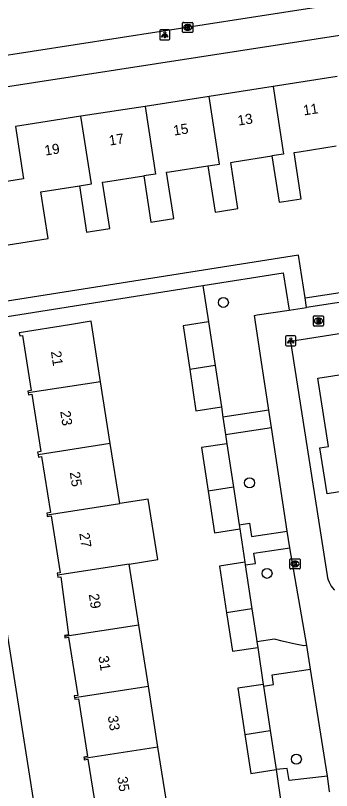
# Model space of a CAD drawing. Extents: x 160077 to 160945, y 386481 to 387498.
# Drawn here: x 160283.4 to 160314.4, y 387277.3 to 387353.4 of the extents above; entities that cross this region are included whole.
import ezdxf

# ---------------------------------------------------------------- set-up
doc = ezdxf.new("R2010")
doc.units = 0
for name, color, linetype in [('IMGEO_Boom', 7, 'Continuous'), ('IMGEO_Brandkraan', 7, 'Continuous'), ('IMGEO_Groenvoorziening', 7, 'Continuous'), ('IMGEO_Haag', 7, 'Continuous'), ('IMGEO_Hek', 7, 'Continuous'), ('IMGEO_Kolk', 7, 'Continuous'), ('IMGEO_Lichtpunt', 7, 'Continuous'), ('IMGEO_Pand', 7, 'Continuous'), ('IMGEO_Pand_nummerreeks', 7, 'Continuous'), ('IMGEO_Rijbaan_lokaal_open', 7, 'Continuous'), ('IMGEO_Voetpad_open', 7, 'Continuous')]:
    doc.layers.add(name, color=color, linetype=linetype)

msp = doc.modelspace()

# ---------------------------------------------------------------- linework, layer by layer
at = {"layer": 'IMGEO_Boom'}
for centre in [(160303.826, 387325.258), (160306.399, 387307.549), (160308.114, 387298.661), (160310.999, 387280.425)]:
    msp.add_circle(centre, 0.489, dxfattribs=at)
at = {"layer": 'IMGEO_Brandkraan'}
for p, q in [((160312.664, 387323.017), (160312.664, 387323.869)), ((160312.739, 387323.943), (160313.591, 387323.943)), ((160313.152, 387323.723), (160313.177, 387323.723)), ((160313.665, 387323.869), (160313.665, 387323.017)), ((160313.591, 387322.943), (160312.739, 387322.943)), ((160313.175, 387323.163), (160313.15, 387323.163))]:
    msp.add_line(p, q, dxfattribs=at)
for points in [[(160312.664, 387323.017), (160312.664, 387323.869)], [(160312.739, 387323.943), (160313.591, 387323.943)], [(160313.012, 387323.643), (160313.012, 387323.243), (160313.225, 387323.243)], [(160313.243, 387323.643), (160313.012, 387323.643)], [(160313.191, 387323.562), (160313.137, 387323.562), (160313.137, 387323.486)], [(160313.137, 387323.486), (160313.19, 387323.486)], [(160313.665, 387323.869), (160313.665, 387323.017)], [(160313.591, 387322.943), (160312.739, 387322.943)], [(160313.199, 387323.41), (160313.137, 387323.41), (160313.137, 387323.329)], [(160313.137, 387323.329), (160313.199, 387323.329)]]:
    msp.add_lwpolyline(points, dxfattribs=at)
for centre, radius, start, end in [((160312.741, 387323.867), 0.0765, 91.55205, 178.44795), ((160312.741, 387323.867), 0.0765, 91.55205, 178.44795), ((160313.192, 387323.524), 0.0379, 267.82845, 90.93552), ((160313.247, 387323.498), 0.145, 59.4692, 91.53667), ((160313.272, 387323.545), 0.0922, 285.51372, 58.15012), ((160313.589, 387323.867), 0.0765, 1.55205, 88.44795), ((160313.589, 387323.867), 0.0765, 1.55205, 88.44795), ((160312.741, 387323.019), 0.0765, 181.55205, 268.44795), ((160312.741, 387323.019), 0.0765, 181.55205, 268.44795), ((160313.2, 387323.369), 0.0404, 269.87594, 90.50774), ((160313.231, 387323.494), 0.251, 268.66757, 293.53466), ((160313.277, 387323.353), 0.105, 301.31148, 78.98903), ((160313.589, 387323.019), 0.0765, 271.55205, 358.44795), ((160313.589, 387323.019), 0.0765, 271.55205, 358.44795)]:
    msp.add_arc(centre, radius, start, end, dxfattribs=at)
for centre, major_axis, ratio, start_param, end_param in [((160313.151, 387323.443), (-0.387, 0.002), 0.722429, 4.712389, 7.853982), ((160313.176, 387323.443), (-0.39, 0.002), 0.717154, 1.570796, 4.712389)]:
    msp.add_ellipse(centre, major_axis=major_axis, ratio=ratio, start_param=start_param, end_param=end_param, dxfattribs=at)
at = {"layer": 'IMGEO_Groenvoorziening'}
for points in [[(160301.814, 387326.925), (160302.357, 387323.353)], [(160303.628, 387314.996), (160303.781, 387313.992)], [(160304.04, 387312.282), (160304.176, 387311.391)]]:
    msp.add_lwpolyline(points, dxfattribs=at)
at = {"layer": 'IMGEO_Haag'}
msp.add_lwpolyline([(160311.864, 387325.704), (160323.038, 387327.4), (160323.143, 387326.454)], dxfattribs=at)
at = {"layer": 'IMGEO_Hek'}
msp.add_lwpolyline([(160311.864, 387325.704), (160323.038, 387327.4)], dxfattribs=at)
at = {"layer": 'IMGEO_Kolk'}
for p, q in [((160299.825, 387351.831), (160299.825, 387352.683)), ((160299.9, 387352.757), (160300.752, 387352.757)), ((160300.313, 387352.537), (160300.338, 387352.537)), ((160300.826, 387352.683), (160300.826, 387351.831)), ((160300.752, 387351.757), (160299.9, 387351.757)), ((160300.336, 387351.977), (160300.311, 387351.977)), ((160310.365, 387299.169), (160310.365, 387300.021)), ((160310.44, 387300.095), (160311.292, 387300.095)), ((160311.366, 387300.021), (160311.366, 387299.169)), ((160310.876, 387299.315), (160310.851, 387299.315)), ((160310.853, 387299.875), (160310.878, 387299.875)), ((160311.292, 387299.095), (160310.44, 387299.095))]:
    msp.add_line(p, q, dxfattribs=at)
for points in [[(160299.825, 387351.831), (160299.825, 387352.683)], [(160299.9, 387352.757), (160300.752, 387352.757)], [(160300.146, 387352.457), (160300.269, 387352.457), (160300.269, 387352.306), (160300.399, 387352.457), (160300.563, 387352.457), (160300.417, 387352.306), (160300.57, 387352.057), (160300.418, 387352.057), (160300.333, 387352.221), (160300.269, 387352.154), (160300.269, 387352.057), (160300.146, 387352.057), (160300.146, 387352.457)], [(160300.826, 387352.683), (160300.826, 387351.831)], [(160300.752, 387351.757), (160299.9, 387351.757)], [(160310.365, 387299.169), (160310.365, 387300.021)], [(160310.44, 387300.095), (160311.292, 387300.095)], [(160311.366, 387300.021), (160311.366, 387299.169)], [(160310.686, 387299.795), (160310.809, 387299.795), (160310.809, 387299.644), (160310.939, 387299.795), (160311.103, 387299.795), (160310.957, 387299.644), (160311.11, 387299.395), (160310.958, 387299.395), (160310.873, 387299.559), (160310.809, 387299.492), (160310.809, 387299.395), (160310.686, 387299.395), (160310.686, 387299.795)], [(160311.292, 387299.095), (160310.44, 387299.095)]]:
    msp.add_lwpolyline(points, dxfattribs=at)
for centre, start, end in [((160299.902, 387352.681), 91.55205, 178.44795), ((160299.902, 387352.681), 91.55205, 178.44795), ((160300.75, 387352.681), 1.55205, 88.44795), ((160300.75, 387352.681), 1.55205, 88.44795), ((160299.902, 387351.833), 181.55205, 268.44795), ((160299.902, 387351.833), 181.55205, 268.44795), ((160300.75, 387351.833), 271.55205, 358.44795), ((160300.75, 387351.833), 271.55205, 358.44795), ((160310.442, 387300.019), 91.55205, 178.44795), ((160310.442, 387300.019), 91.55205, 178.44795), ((160311.29, 387300.019), 1.55205, 88.44795), ((160311.29, 387300.019), 1.55205, 88.44795), ((160310.442, 387299.171), 181.55205, 268.44795), ((160310.442, 387299.171), 181.55205, 268.44795), ((160311.29, 387299.171), 271.55205, 358.44795), ((160311.29, 387299.171), 271.55205, 358.44795)]:
    msp.add_arc(centre, 0.0765, start, end, dxfattribs=at)
for centre, major_axis, ratio, start_param, end_param in [((160300.312, 387352.257), (-0.387, 0.002), 0.722429, 4.712389, 7.853982), ((160300.337, 387352.257), (-0.39, 0.002), 0.717154, 1.570796, 4.712389), ((160310.852, 387299.595), (-0.387, 0.002), 0.722429, 4.712389, 7.853982), ((160310.877, 387299.595), (-0.39, 0.002), 0.717154, 1.570796, 4.712389)]:
    msp.add_ellipse(centre, major_axis=major_axis, ratio=ratio, start_param=start_param, end_param=end_param, dxfattribs=at)
at = {"layer": 'IMGEO_Lichtpunt'}
for p, q in [((160297.57, 387351.936), (160297.57, 387351.129)), ((160297.57, 387351.936), (160297.57, 387351.129)), ((160298.472, 387352.031), (160297.664, 387352.031)), ((160298.472, 387352.031), (160297.664, 387352.031)), ((160298.566, 387351.129), (160298.566, 387351.936)), ((160298.566, 387351.129), (160298.566, 387351.936)), ((160297.664, 387351.035), (160298.472, 387351.035)), ((160297.664, 387351.035), (160298.472, 387351.035)), ((160310.846, 387321.987), (160310.038, 387321.987)), ((160310.846, 387321.987), (160310.038, 387321.987)), ((160309.944, 387321.892), (160309.944, 387321.085)), ((160309.944, 387321.892), (160309.944, 387321.085)), ((160310.94, 387321.085), (160310.94, 387321.892)), ((160310.94, 387321.085), (160310.94, 387321.892)), ((160310.038, 387320.991), (160310.846, 387320.991)), ((160310.038, 387320.991), (160310.846, 387320.991))]:
    msp.add_line(p, q, dxfattribs=at)
for points in [[(160297.944, 387351.6), (160297.983, 387351.572), (160297.795, 387351.31), (160297.757, 387351.337), (160297.944, 387351.6)], [(160298.046, 387351.552), (160298.093, 387351.552), (160298.093, 387351.23), (160298.046, 387351.23), (160298.046, 387351.552)], [(160298.156, 387351.572), (160298.194, 387351.599), (160298.381, 387351.337), (160298.342, 387351.309), (160298.156, 387351.572)], [(160310.318, 387321.556), (160310.357, 387321.528), (160310.169, 387321.266), (160310.131, 387321.293), (160310.318, 387321.556)], [(160310.42, 387321.508), (160310.467, 387321.508), (160310.467, 387321.186), (160310.42, 387321.186), (160310.42, 387321.508)], [(160310.53, 387321.528), (160310.568, 387321.555), (160310.755, 387321.293), (160310.716, 387321.265), (160310.53, 387321.528)]]:
    msp.add_lwpolyline(points, dxfattribs=at)
for centre in [(160298.069, 387351.734), (160310.443, 387321.69)]:
    msp.add_circle(centre, 0.0994, dxfattribs=at)
for centre, start, end in [((160297.664, 387351.936), 90, 180), ((160297.664, 387351.936), 90, 180), ((160298.472, 387351.936), 0, 90), ((160298.472, 387351.936), 0, 90), ((160297.664, 387351.129), 180, 270), ((160297.664, 387351.129), 180, 270), ((160298.472, 387351.129), 270, 0), ((160298.472, 387351.129), 270, 360), ((160310.038, 387321.892), 90, 180), ((160310.038, 387321.892), 90, 180), ((160310.846, 387321.892), 0, 90), ((160310.846, 387321.892), 0, 90), ((160310.038, 387321.085), 180, 270), ((160310.038, 387321.085), 180, 270), ((160310.846, 387321.085), 270, 0), ((160310.846, 387321.085), 270, 360)]:
    msp.add_arc(centre, 0.0946, start, end, dxfattribs=at)
at = {"layer": 'IMGEO_Pand'}
for points in [[(160315.01, 387347.441), (160308.715, 387346.464)], [(160308.715, 387346.464), (160302.42, 387345.486)], [(160308.715, 387346.464), (160309.747, 387339.817), (160308.596, 387339.638)], [(160302.42, 387345.486), (160296.126, 387344.509)], [(160302.299, 387338.662), (160303.452, 387338.839), (160302.42, 387345.486)], [(160296.126, 387344.509), (160289.831, 387343.531)], [(160296.126, 387344.509), (160297.158, 387337.865), (160295.999, 387337.684)], [(160289.831, 387343.531), (160283.396, 387342.532), (160284.197, 387337.379), (160280.249, 387336.766), (160281.193, 387330.687), (160286.6, 387331.526), (160285.887, 387336.114), (160289.677, 387336.703)], [(160289.677, 387336.703), (160290.862, 387336.887), (160289.831, 387343.531)], [(160308.596, 387339.638), (160309.301, 387335.096), (160309.752, 387335.166), (160311.477, 387335.434), (160310.771, 387339.978), (160311.274, 387340.056), (160314.892, 387340.618)], [(160302.299, 387338.662), (160303.004, 387334.119), (160303.459, 387334.19), (160305.249, 387334.468), (160304.543, 387339.011), (160304.902, 387339.067), (160308.596, 387339.638)], [(160295.999, 387337.684), (160296.705, 387333.141), (160297.097, 387333.202), (160298.955, 387333.49), (160298.249, 387338.034), (160298.519, 387338.076), (160302.299, 387338.662)], [(160289.677, 387336.703), (160290.383, 387332.159), (160290.783, 387332.221), (160292.661, 387332.513), (160291.955, 387337.056), (160292.25, 387337.102), (160295.999, 387337.684)], [(160291.759, 387317.481), (160290.828, 387323.406), (160288.707, 387323.071), (160283.768, 387322.29), (160283.818, 387321.973), (160284.079, 387322.015), (160284.935, 387316.602), (160284.617, 387316.552), (160284.644, 387316.378)], [(160302.357, 387323.353), (160299.861, 387322.974), (160300.516, 387318.668)], [(160302.357, 387323.353), (160303.011, 387319.054)], [(160303.011, 387319.054), (160300.516, 387318.668)], [(160303.011, 387319.054), (160303.628, 387314.996)], [(160300.516, 387318.668), (160301.133, 387314.617), (160303.628, 387314.996)], [(160319.696, 387311.979), (160315.535, 387311.328), (160316.239, 387306.829), (160314.021, 387306.482), (160313.317, 387310.981), (160314.16, 387311.113), (160313.112, 387317.809), (160319.627, 387318.828)], [(160291.759, 387317.481), (160284.644, 387316.378)], [(160292.712, 387311.415), (160291.759, 387317.481)], [(160284.644, 387316.378), (160284.672, 387316.203), (160284.998, 387316.255), (160285.89, 387310.612), (160285.576, 387310.562), (160285.615, 387310.315)], [(160292.712, 387311.415), (160285.615, 387310.315)], [(160293.639, 387305.518), (160292.712, 387311.415)], [(160304.176, 387311.391), (160301.682, 387311.012), (160302.335, 387306.725)], [(160304.176, 387311.391), (160304.827, 387307.111)], [(160285.615, 387310.315), (160285.654, 387310.069), (160285.972, 387310.12), (160286.838, 387304.637), (160286.472, 387304.579), (160286.499, 387304.412)], [(160304.827, 387307.111), (160302.335, 387306.725)], [(160304.827, 387307.111), (160305.387, 387303.426)], [(160302.335, 387306.725), (160302.956, 387302.642), (160305.449, 387303.021)], [(160286.499, 387304.412), (160293.639, 387305.518)], [(160294.572, 387299.579), (160297.374, 387300.013), (160296.441, 387305.952), (160293.639, 387305.518)], [(160286.499, 387304.412), (160286.525, 387304.247), (160286.899, 387304.306), (160287.78, 387298.731), (160287.496, 387298.686), (160287.527, 387298.488)], [(160305.387, 387303.426), (160305.449, 387303.021)], [(160294.572, 387299.579), (160287.527, 387298.488)], [(160295.515, 387293.578), (160294.572, 387299.579)], [(160305.938, 387299.762), (160303.444, 387299.383), (160304.144, 387294.781)], [(160305.938, 387299.762), (160305.98, 387299.487)], [(160305.98, 387299.487), (160306.637, 387295.167)], [(160287.527, 387298.488), (160287.558, 387298.292), (160287.846, 387298.337), (160288.606, 387292.634), (160288.213, 387292.571), (160288.233, 387292.45)], [(160306.637, 387295.167), (160304.144, 387294.781)], [(160304.144, 387294.781), (160304.718, 387291.013), (160307.211, 387291.392)], [(160306.637, 387295.167), (160307.083, 387292.233), (160307.127, 387291.941)], [(160295.515, 387293.578), (160288.233, 387292.45)], [(160296.456, 387287.591), (160295.515, 387293.578)], [(160288.233, 387292.45), (160288.252, 387292.331), (160288.616, 387292.389), (160289.527, 387286.688), (160289.181, 387286.632), (160289.207, 387286.468)], [(160307.127, 387291.941), (160307.211, 387291.392)], [(160307.739, 387287.769), (160305.245, 387287.39), (160305.938, 387282.835)], [(160307.739, 387287.769), (160307.764, 387287.603)], [(160289.207, 387286.468), (160296.456, 387287.591)], [(160297.396, 387281.609), (160296.456, 387287.591)], [(160307.764, 387287.603), (160308.431, 387283.221)], [(160289.207, 387286.468), (160289.233, 387286.305), (160289.577, 387286.36), (160290.485, 387280.678), (160290.121, 387280.619), (160290.143, 387280.485)], [(160305.938, 387282.835), (160308.431, 387283.221)], [(160308.431, 387283.221), (160309.012, 387279.399)], [(160305.938, 387282.835), (160306.519, 387279.02), (160309.012, 387279.399)], [(160297.396, 387281.609), (160290.143, 387280.485)], [(160298.33, 387275.664), (160297.396, 387281.609)], [(160290.143, 387280.485), (160290.164, 387280.352), (160290.512, 387280.408), (160291.419, 387274.733), (160291.067, 387274.676), (160291.088, 387274.542)]]:
    msp.add_lwpolyline(points, dxfattribs=at)
at = {"layer": 'IMGEO_Rijbaan_lokaal_open'}
msp.add_lwpolyline([(160324.17, 387355.972), (160306.164, 387353.162), (160276.556, 387348.583)], dxfattribs=at)
at = {"layer": 'IMGEO_Voetpad_open'}
for points in [[(160277.066, 387345.597), (160345.165, 387356.158)], [(160311.864, 387325.704), (160311.213, 387329.893), (160277.587, 387324.592)], [(160301.814, 387326.925), (160309.705, 387328.169), (160310.282, 387324.506)], [(160352.153, 387327.971), (160310.416, 387321.441), (160314.017, 387298.456), (160314.061, 387298.234), (160314.124, 387298.017), (160314.206, 387297.806), (160314.307, 387297.603), (160314.426, 387297.41), (160314.561, 387297.229), (160314.712, 387297.06), (160314.749, 387297.023)], [(160277.816, 387323.142), (160301.814, 387326.925)], [(160323.143, 387326.454), (160312.006, 387324.767)], [(160312.006, 387324.767), (160311.864, 387325.704)], [(160308.303, 387314.677), (160307.652, 387318.96), (160306.887, 387323.99), (160307.144, 387324.03), (160310.282, 387324.506)], [(160310.282, 387324.506), (160312.006, 387324.767)], [(160291.461, 387236.621), (160289.345, 387250), (160287.045, 387264.59), (160277.816, 387323.142)], [(160308.303, 387314.677), (160303.781, 387313.992)], [(160308.563, 387312.97), (160308.303, 387314.677)], [(160303.781, 387313.992), (160304.04, 387312.282)], [(160304.04, 387312.282), (160308.563, 387312.97)], [(160310.106, 387302.817), (160308.563, 387312.97)], [(160305.387, 387303.426), (160306.383, 387303.577), (160306.577, 387302.281), (160310.106, 387302.817)], [(160305.449, 387303.021), (160305.938, 387299.762)], [(160310.355, 387301.177), (160310.106, 387302.817)], [(160305.98, 387299.487), (160306.974, 387299.638), (160306.824, 387300.64), (160310.355, 387301.177)], [(160312.04, 387291.582), (160310.355, 387301.177)], [(160312.04, 387291.582), (160311.717, 387291.548), (160310.746, 387291.754), (160309.603, 387292.011), (160308.838, 387292.219), (160307.127, 387291.941)], [(160312.395, 387289.271), (160312.04, 387291.582)], [(160307.211, 387291.392), (160307.739, 387287.769)], [(160307.764, 387287.603), (160308.764, 387287.755), (160308.627, 387288.698), (160312.395, 387289.271)], [(160314.048, 387278.741), (160312.395, 387289.271)], [(160314.048, 387278.741), (160310.274, 387278.345), (160310.106, 387279.495), (160309.012, 387279.399)], [(160309.012, 387279.399), (160309.54, 387275.779)], [(160314.271, 387277.218), (160314.268, 387277.238), (160314.048, 387278.741)]]:
    msp.add_lwpolyline(points, dxfattribs=at)

# ---------------------------------------------------------------- texts
at = {"layer": 'IMGEO_Pand_nummerreeks'}
for s, rotation, p in [('11', 8.82928, (160311.737, 387343.613)), ('13', 8.82928, (160305.301, 387342.615)), ('15', 8.82928, (160298.979, 387341.633)), ('17', 8.82928, (160292.656, 387340.651)), ('19', 8.82928, (160286.333, 387339.669)), ('21', 278.86949, (160286.875, 387320.433)), ('23', 278.86949, (160287.792, 387314.559)), ('25', 278.86949, (160288.726, 387308.573)), ('27', 278.86918, (160289.66, 387302.587)), ('29', 278.86949, (160290.594, 387296.603)), ('31', 278.86949, (160291.545, 387290.506)), ('33', 278.86949, (160292.462, 387284.632)), ('35', 278.86949, (160293.396, 387278.647))]:
    msp.add_text(s, height=1, rotation=rotation, dxfattribs=at).set_placement(p)

doc.saveas('drawing.dxf')
